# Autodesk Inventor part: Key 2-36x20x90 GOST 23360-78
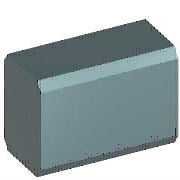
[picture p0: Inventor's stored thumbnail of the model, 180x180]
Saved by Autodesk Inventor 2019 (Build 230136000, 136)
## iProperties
Created: 2018-01
Part Number: Key 2-36x20x90 GOST 23360-78
Material: Steel, Mild
Description: Keyed joints with sunk keys
Document SubType Name: Modeling
Standard: GOST 23360-78 (2)
Designer: m.vorobev
Standards Organization: GOST
Language: en-US
Size Designation: 36 x 20 x 90
Categories: <MemberInstance><Categories><Category DisplayName="Shaft Parts" InternalName="7f7aeb1f-a693-4053-b835-cee3144e0d98" Mnemonic="SHFT"><Category DisplayName="Keys"
Density: 7.85 g/cm^3
Appearance: Semi-Polished
IsCustomPart: 0
Author: m.vorobev
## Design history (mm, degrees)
sketch "Sketch1"
  geometry: L1 (18, 18)-(108, 18); L2 (108, 18)-(108, -18); L3 (108, -18)-(18, -18); L4 (0, 7)-(0, -7) reference; L5 (-6, 0)-(36, 0) reference; L6 (18, 18)-(18, -18); A1 r 18 centre (18, 0) between (18, 18) and (18, -18)
  constraints: 8 end point, 3 tangent, 2 perpendicular, 2 point on circle, 1 centre point, 1 horizontal, 1 parallel, 1 point on line
  dimensions: "d0" = 18 radius of A1 (= 0.5 x PB); "d19" = 90 distance of L1.start L1.end (= NLG)
extrude "Body1" new body sketch "Sketch1" taper "d3" = 0 deg; stored distance "d4" = 10
body "Solid1"
workplane "Work Plane1"
workplane "Work Plane2"
chamfer "Chamfer1" distance "d8" = 1 (= PHH); stored, may be unused: second distance "d9" = 1 (= PHH), angle "d13" = 45 deg
other parameters: "d1" = -12 (= -PNT), "d2" = 8 (= PH - PNT), "NLG" = 90 [user parameter; used in 1 equation term], "PB" = 36 [user parameter; used in 1 equation term], "PNT" = 12 [user parameter; used in 2 equation terms], "PHH" = 1 [user parameter; used in 2 equation terms], "d10" = 0, "d16" = 0, "d17" = 0, "d18" = 0, "RR" = 0.7 [user parameter], "PLB1" = 108 [user parameter], "PLB2" = 126 [user parameter], "PUEB" = 8.4 [user parameter]
